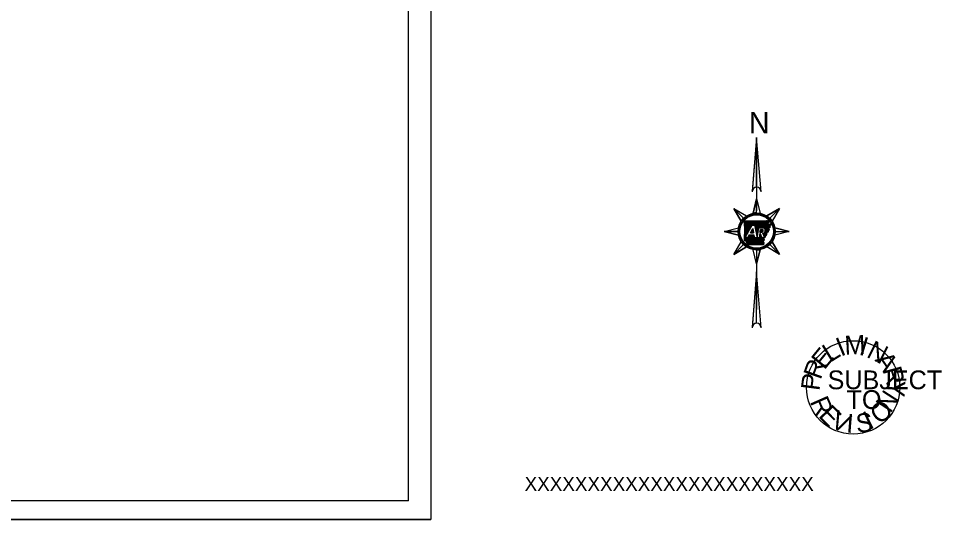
# Model space of a CAD drawing. Extents: x 1644315 to 1648839, y 578550 to 581749.
# Drawn here: x 1646874 to 1648839, y 578550 to 579616 of the extents above; entities that cross this region are included whole.
import ezdxf

# ---------------------------------------------------------------- set-up
doc = ezdxf.new("R2010")
doc.units = 0
for name, color, linetype in [('20', 7, 'Continuous'), ('R_Border PE', 7, 'Continuous'), ('R_Border Prem', 7, 'Continuous')]:
    doc.layers.add(name, color=color, linetype=linetype)

msp = doc.modelspace()

# ---------------------------------------------------------------- linework, layer by layer
at = {"layer": '20'}
msp.add_line((1644418.6, 578549.8), (1647751.9, 578549.8), dxfattribs=at)
msp.add_lwpolyline([(1644418.5, 580683.1), (1647751.9, 580683.1), (1647751.9, 578549.7), (1644418.5, 578549.7)], close=True, dxfattribs=at)
at = {"layer": 'R_Border PE'}
for q in [(1647704.4, 580644.2), (1644542.6, 578589.6)]:
    msp.add_line((1647704.4, 578589.6), q, dxfattribs=at)
at = {"layer": 'R_Border Prem'}
for p, q in [((1648445.2, 579362.9), (1648435.5, 579248.9)), ((1648445.2, 579362.9), (1648445.2, 579206.8)), ((1648445.2, 579257.1), (1648445.2, 579362.9)), ((1648435.6, 579250.5), (1648436.1, 579251)), ((1648435.7, 579251.1), (1648436.6, 579252)), ((1648445.2, 579232.2), (1648437.5, 579201.8)), ((1648445.2, 579202.5), (1648445.2, 579232.2)), ((1648396.3, 579211.9), (1648417.3, 579191)), ((1648417.3, 579191), (1648396.3, 579211.9)), ((1648396.3, 579211.9), (1648412.4, 579185)), ((1648494.1, 579211.9), (1648467.2, 579195.9)), ((1648473.2, 579191), (1648494.1, 579211.9)), ((1648473.2, 579191), (1648494.1, 579211.9)), ((1648418.3, 579185.3), (1648418.6, 579185.6)), ((1648418.4, 579184.3), (1648419.8, 579185.6)), ((1648418.5, 579183.3), (1648420.9, 579185.6)), ((1648418.7, 579182.3), (1648422, 579185.6)), ((1648418.8, 579181.3), (1648423.1, 579185.6)), ((1648418.9, 579180.3), (1648424.2, 579185.6)), ((1648419, 579179.3), (1648425.4, 579185.6)), ((1648419.2, 579178.3), (1648426.5, 579185.6)), ((1648419.3, 579177.3), (1648427.6, 579185.6)), ((1648419.4, 579176.3), (1648428.7, 579185.6)), ((1648419.5, 579175.3), (1648429.8, 579185.6)), ((1648419.7, 579174.3), (1648430.9, 579185.6)), ((1648419.8, 579173.4), (1648432.1, 579185.6)), ((1648419.9, 579161.2), (1648444.4, 579185.6)), ((1648419.9, 579172.4), (1648433.2, 579185.6)), ((1648419.9, 579160.1), (1648435, 579175.1)), ((1648419.9, 579158.9), (1648433.5, 579172.6)), ((1648420, 579162.4), (1648443.3, 579185.6)), ((1648420, 579163.5), (1648442.1, 579185.6)), ((1648420, 579171.4), (1648434.3, 579185.6)), ((1648420.1, 579164.7), (1648441, 579185.6)), ((1648420.1, 579165.8), (1648439.9, 579185.6)), ((1648420.1, 579167), (1648438.8, 579185.6)), ((1648420.2, 579168.2), (1648437.7, 579185.6)), ((1648420.2, 579169.3), (1648436.5, 579185.6)), ((1648420.2, 579170.4), (1648435.4, 579185.6)), ((1648420.3, 579149.2), (1648435.9, 579176.7)), ((1648435.9, 579176.7), (1648440.5, 579176.7)), ((1648436.5, 579176.7), (1648445.5, 579185.6)), ((1648437.7, 579176.7), (1648446.6, 579185.6)), ((1648438.8, 579176.7), (1648447.7, 579185.7)), ((1648439.9, 579176.7), (1648448.9, 579185.7)), ((1648440.6, 579176.3), (1648450, 579185.7)), ((1648440.8, 579175.4), (1648451.1, 579185.7)), ((1648441, 579174.4), (1648452.3, 579185.7)), ((1648441.2, 579173.5), (1648453.4, 579185.7)), ((1648441.4, 579172.6), (1648454.6, 579185.8)), ((1648441.6, 579171.7), (1648455.7, 579185.8)), ((1648441.8, 579170.8), (1648456.8, 579185.8)), ((1648442, 579169.8), (1648458, 579185.8)), ((1648442.2, 579168.9), (1648459.1, 579185.8)), ((1648442.4, 579168), (1648460.2, 579185.9)), ((1648442.6, 579167.1), (1648461.4, 579185.9)), ((1648442.8, 579166.2), (1648462.5, 579185.9)), ((1648443, 579165.2), (1648463.6, 579185.9)), ((1648443.2, 579164.3), (1648464.8, 579185.9)), ((1648449.9, 579171), (1648460.7, 579171)), ((1648450.9, 579171), (1648465.9, 579186)), ((1648452, 579171), (1648467.1, 579186)), ((1648453.2, 579171), (1648468.2, 579186)), ((1648454.3, 579171), (1648469.4, 579186)), ((1648455.4, 579171), (1648470.5, 579186.1)), ((1648456.5, 579171), (1648470.8, 579185.2)), ((1648457.6, 579171), (1648471.3, 579184.6)), ((1648458.7, 579171), (1648471.4, 579183.6)), ((1648459.9, 579171), (1648468.9, 579180)), ((1648460.9, 579170.9), (1648468.7, 579178.6)), ((1648461.5, 579170.3), (1648469.8, 579178.7)), ((1648462, 579169.8), (1648471, 579178.8)), ((1648462.5, 579169.1), (1648472.2, 579178.8)), ((1648462.9, 579168.4), (1648473.4, 579178.9)), ((1648463.3, 579167.7), (1648474.6, 579178.9)), ((1648463.5, 579166.8), (1648475.6, 579178.9)), ((1648463.5, 579163.4), (1648473.6, 579173.5)), ((1648463.7, 579165.8), (1648476.1, 579178.3)), ((1648463.7, 579164.7), (1648473.5, 579174.5)), ((1648472.4, 579171.1), (1648473.7, 579172.5)), ((1648475.6, 579176.7), (1648476.7, 579177.7)), ((1648514.4, 579163), (1648484, 579170.7)), ((1648376.1, 579163), (1648405.7, 579163)), ((1648405.7, 579163), (1648376.1, 579163)), ((1648376.1, 579163), (1648406.5, 579155.3)), ((1648419.6, 579152), (1648424.8, 579157.1)), ((1648419.6, 579150.8), (1648423.3, 579154.5)), ((1648419.6, 579149.7), (1648421.9, 579152)), ((1648419.7, 579154.3), (1648427.7, 579162.3)), ((1648419.7, 579153.1), (1648426.2, 579159.7)), ((1648419.8, 579157.8), (1648432.1, 579170)), ((1648419.8, 579156.6), (1648430.6, 579167.4)), ((1648419.8, 579155.4), (1648429.2, 579164.8)), ((1648419.8, 579143.2), (1648431.6, 579154.9)), ((1648420.5, 579142.7), (1648432.7, 579154.9)), ((1648421.3, 579142.4), (1648433.8, 579154.9)), ((1648422.6, 579142.6), (1648434.9, 579154.9)), ((1648423.7, 579142.7), (1648436, 579154.9)), ((1648424.6, 579141.3), (1648438.3, 579154.9)), ((1648424.6, 579142.4), (1648437.1, 579154.9)), ((1648424.7, 579140.2), (1648439.4, 579154.9)), ((1648424.7, 579139.1), (1648440, 579154.4)), ((1648424.7, 579138), (1648440.2, 579153.5)), ((1648424.7, 579136.9), (1648440.4, 579152.6)), ((1648424.7, 579135.8), (1648440.6, 579151.7)), ((1648424.7, 579134.7), (1648440.8, 579150.7)), ((1648428.9, 579154.9), (1648425.6, 579149.2)), ((1648426.9, 579151.4), (1648430.4, 579154.9)), ((1648428.4, 579154), (1648429.3, 579154.9)), ((1648439.9, 579154.9), (1648428.9, 579154.9)), ((1648431.8, 579160), (1648436.9, 579169)), ((1648431.8, 579160), (1648437.5, 579165.7)), ((1648431.8, 579160), (1648438.8, 579160)), ((1648432.9, 579160), (1648437.7, 579164.8)), ((1648433.1, 579162.4), (1648437.4, 579166.6)), ((1648434, 579160), (1648437.9, 579163.9)), ((1648434.6, 579165), (1648437.2, 579167.6)), ((1648435.2, 579160), (1648438.1, 579163)), ((1648435.8, 579134.6), (1648455.1, 579153.9)), ((1648436.1, 579167.6), (1648437, 579168.5)), ((1648436.3, 579160), (1648438.3, 579162)), ((1648437, 579134.6), (1648455.4, 579153)), ((1648437.4, 579160), (1648438.5, 579161.1)), ((1648438.1, 579134.6), (1648455.7, 579152.2)), ((1648438.5, 579160), (1648438.7, 579160.2)), ((1648439.2, 579134.6), (1648456, 579151.4)), ((1648440.3, 579134.6), (1648456.3, 579150.6)), ((1648443.4, 579163.4), (1648449.7, 579169.7)), ((1648443.6, 579162.5), (1648449.5, 579168.4)), ((1648443.7, 579161.5), (1648449.2, 579167)), ((1648443.9, 579160.6), (1648449, 579165.7)), ((1648444.1, 579159.7), (1648448.8, 579164.3)), ((1648444.3, 579158.8), (1648448.5, 579163)), ((1648444.5, 579157.9), (1648448.3, 579161.6)), ((1648444.7, 579156.9), (1648448, 579160.3)), ((1648444.9, 579156), (1648447.8, 579158.9)), ((1648445.1, 579155.1), (1648447.6, 579157.5)), ((1648445.3, 579154.2), (1648447.3, 579156.2)), ((1648445.5, 579153.3), (1648447.1, 579154.8)), ((1648445.7, 579152.3), (1648446.9, 579153.5)), ((1648445.9, 579151.4), (1648446.6, 579152.1)), ((1648446.1, 579150.5), (1648446.4, 579150.8)), ((1648450.4, 579150.3), (1648454.8, 579154.7)), ((1648450.6, 579151.6), (1648454.5, 579155.5)), ((1648450.8, 579153), (1648454.2, 579156.3)), ((1648451.1, 579154.3), (1648453.9, 579157.1)), ((1648451.3, 579155.7), (1648453.5, 579157.9)), ((1648451.5, 579157), (1648452.4, 579157.9)), ((1648453.6, 579157.9), (1648451.7, 579157.9)), ((1648452.3, 579161.2), (1648458.1, 579167.1)), ((1648452.3, 579161.2), (1648456.9, 579161.2)), ((1648452.5, 579162.5), (1648457, 579167.1)), ((1648452.7, 579163.9), (1648455.9, 579167.1)), ((1648453, 579165.2), (1648454.8, 579167.1)), ((1648453.2, 579166.6), (1648453.7, 579167.1)), ((1648453.3, 579167.1), (1648458.4, 579167.1)), ((1648453.4, 579161.2), (1648458.8, 579166.6)), ((1648456.8, 579149.2), (1648453.6, 579157.9)), ((1648454.5, 579161.2), (1648459.1, 579165.8)), ((1648455.6, 579161.2), (1648459.4, 579164.9)), ((1648456.7, 579161.2), (1648459.3, 579163.7)), ((1648458.2, 579158.2), (1648458.6, 579158.5)), ((1648458.2, 579158.4), (1648461.6, 579149.2)), ((1648458.5, 579157.3), (1648460.7, 579159.5)), ((1648458.8, 579156.5), (1648471.2, 579168.9)), ((1648459.1, 579155.7), (1648471.4, 579168)), ((1648459.4, 579154.9), (1648471.7, 579167.1)), ((1648459.7, 579154.1), (1648471.9, 579166.2)), ((1648460, 579153.3), (1648466.8, 579160)), ((1648460.4, 579152.4), (1648466.6, 579158.7)), ((1648460.7, 579151.6), (1648466.5, 579157.5)), ((1648461, 579150.8), (1648464.4, 579154.2)), ((1648461.3, 579150), (1648463.9, 579152.6)), ((1648462.5, 579161.3), (1648471, 579169.8)), ((1648468, 579161.2), (1648469.6, 579162.8)), ((1648484.8, 579163), (1648514.4, 579163)), ((1648484.8, 579163), (1648514.4, 579163)), ((1648396.3, 579114.1), (1648417.3, 579135.1)), ((1648417.3, 579135.1), (1648396.3, 579114.1)), ((1648419.4, 579143.9), (1648424.7, 579149.2)), ((1648419.4, 579145), (1648423.5, 579149.2)), ((1648419.4, 579146.2), (1648422.4, 579149.2)), ((1648419.5, 579148.5), (1648420.4, 579149.4)), ((1648419.5, 579147.3), (1648421.3, 579149.2)), ((1648425.6, 579149.2), (1648420.3, 579149.2)), ((1648425.8, 579134.7), (1648441, 579149.8)), ((1648426.9, 579134.7), (1648441.4, 579149.2)), ((1648428, 579134.7), (1648442.5, 579149.2)), ((1648429.1, 579134.6), (1648443.7, 579149.2)), ((1648430.3, 579134.6), (1648444.8, 579149.2)), ((1648431.4, 579134.6), (1648445.9, 579149.2)), ((1648432.5, 579134.6), (1648447, 579149.2)), ((1648433.6, 579134.6), (1648448.1, 579149.2)), ((1648434.7, 579134.6), (1648449.3, 579149.2)), ((1648450.2, 579149.2), (1648441.1, 579149.2)), ((1648441.4, 579134.6), (1648456.6, 579149.8)), ((1648442.5, 579134.6), (1648457.1, 579149.2)), ((1648443.7, 579134.6), (1648458.2, 579149.2)), ((1648444.8, 579134.6), (1648459.3, 579149.2)), ((1648445.9, 579134.6), (1648460.4, 579149.2)), ((1648447, 579134.6), (1648460.8, 579148.4)), ((1648448.1, 579134.6), (1648460.9, 579147.4)), ((1648449.2, 579134.6), (1648460.9, 579146.3)), ((1648450.4, 579134.6), (1648461, 579145.2)), ((1648451.5, 579134.6), (1648459.1, 579142.3)), ((1648452.6, 579134.6), (1648459.5, 579141.5)), ((1648453.7, 579134.6), (1648459.8, 579140.7)), ((1648454.8, 579134.6), (1648460.2, 579139.9)), ((1648455.9, 579134.6), (1648460.5, 579139.2)), ((1648461.6, 579149.2), (1648456.8, 579149.2)), ((1648457, 579134.6), (1648460.8, 579138.3)), ((1648458.2, 579134.6), (1648460.3, 579136.7)), ((1648459.3, 579134.6), (1648459.8, 579135.1)), ((1648473.2, 579135.1), (1648494.1, 579114.1)), ((1648473.2, 579135.1), (1648494.1, 579114.1)), ((1648494.1, 579114.1), (1648478.1, 579141)), ((1648396.3, 579114.1), (1648423.3, 579130.2)), ((1648445.2, 579093.8), (1648452.9, 579124.2)), ((1648445.2, 579123.5), (1648445.2, 579123.5)), ((1648445.2, 579123.5), (1648445.2, 578997)), ((1648445.2, 579123.5), (1648445.2, 579093.8)), ((1648445.2, 579077.3), (1648435.5, 578959.4)), ((1648445.2, 578967.7), (1648445.2, 579077.3))]:
    msp.add_line(p, q, dxfattribs=at)
for points in [[(1648455.1, 579247.3), (1648445.2, 579362.9), (1648435.4, 579247.3)], [(1648437.5, 579201.8), (1648445.2, 579232.2), (1648452.9, 579201.8)], [(1648412.4, 579185), (1648396.3, 579211.9), (1648423.3, 579195.9)], [(1648467.2, 579195.9), (1648494.1, 579211.9), (1648478.1, 579185)], [(1648406.5, 579155.3), (1648376.1, 579163), (1648406.5, 579170.7)], [(1648418.3, 579185.6), (1648433.7, 579185.6), (1648447.2, 579185.7), (1648463.2, 579185.9), (1648470.6, 579186.1)], [(1648419.4, 579143.9), (1648420.2, 579169.8), (1648418.3, 579185.6)], [(1648440.5, 579176.7), (1648446.2, 579149.9), (1648449.9, 579171)], [(1648475.4, 579179), (1648476.8, 579177.6), (1648473.4, 579174.9), (1648473.8, 579172.1), (1648470.9, 579170.2), (1648471.9, 579166), (1648469.7, 579164), (1648469.5, 579161.8), (1648466.8, 579160.8), (1648466.4, 579156.7), (1648464.5, 579154.6), (1648463.6, 579151.5), (1648460.8, 579149), (1648461, 579144.5), (1648459.1, 579142.3), (1648460.8, 579138.5), (1648459.6, 579134.6)], [(1648468.3, 579178.6), (1648475.5, 579179)], [(1648484, 579170.7), (1648514.4, 579163), (1648484, 579155.3)], [(1648436.9, 579169), (1648438.8, 579160)], [(1648441.1, 579149.2), (1648439.9, 579154.9)], [(1648451.7, 579157.9), (1648450.2, 579149.2)], [(1648452.3, 579161.2), (1648453.3, 579167.1)], [(1648423.3, 579130.2), (1648396.3, 579114.1), (1648412.4, 579141)], [(1648459.6, 579134.6), (1648424.7, 579134.7), (1648424.6, 579142.4)], [(1648478.1, 579141), (1648494.1, 579114.1), (1648467.2, 579130.2)], [(1648452.9, 579124.2), (1648445.2, 579093.8), (1648437.5, 579124.2)], [(1648455.1, 578957.8), (1648445.2, 579077.3), (1648435.4, 578957.8)]]:
    msp.add_lwpolyline(points, dxfattribs=at)
for centre, radius in [((1648445.2, 579163), 39.5), ((1648445.2, 579163), 37.5), ((1648445.2, 579163), 35.6), ((1648650.6, 578831.1), 99.4)]:
    msp.add_circle(centre, radius, dxfattribs=at)
for centre, radius, start, end in [((1648445.2, 579247.3), 9.88, 0, 180), ((1648445.2, 579247.3), 9.88, 90, 170.2296), ((1648445.2, 579163), 39.5, 135, 146.2291), ((1648445.2, 579163), 39.5, 90, 101.2291), ((1648445.2, 579163), 39.5, 45, 56.2291), ((1648456.7, 579165.2), 7, 281.8626, 54.8705), ((1648445.2, 579163), 39.5, 0, 11.2291), ((1648445.2, 579163), 39.5, 180, 191.2291), ((1648455.8, 579164.6), 3.58, 288.1268, 43.8902), ((1648445.2, 579163), 39.5, 225, 236.2291), ((1648445.2, 579163), 39.5, 315, 326.2291), ((1648445.2, 579163), 39.5, 270, 281.2291), ((1648445.2, 578957.8), 9.88, 0, 180), ((1648445.2, 578957.8), 9.88, 90, 170.5511)]:
    msp.add_arc(centre, radius, start, end, dxfattribs=at)
for points in [[(1648470.6, 579186.1), (1648470.6, 579185.7), (1648470.8, 579185.4), (1648470.8, 579185), (1648470.9, 579184.9), (1648471.2, 579184.7), (1648471.5, 579184.4), (1648471.5, 579184.1), (1648471.4, 579183.8), (1648471.4, 579183.4), (1648471.4, 579183.1), (1648471.3, 579182.8), (1648471.1, 579182.5), (1648470.9, 579182.4), (1648470.7, 579182.2), (1648470.5, 579181.9), (1648470.3, 579181.7), (1648470, 579181.5), (1648469.8, 579181.3), (1648469.6, 579181), (1648469.5, 579180.7), (1648469.3, 579180.5), (1648469.2, 579180.3), (1648468.9, 579180), (1648468.8, 579179.8), (1648468.6, 579179.5), (1648468.5, 579179.2), (1648468.4, 579179), (1648468.4, 579178.9)], [(1648424.6, 579142.4), (1648424.7, 579142.4), (1648424.5, 579142.5), (1648424.3, 579142.6), (1648424, 579142.6), (1648423.6, 579142.7), (1648423.3, 579142.7), (1648423, 579142.9), (1648422.7, 579142.7), (1648422.3, 579142.5), (1648422.1, 579142.7), (1648421.9, 579142.6), (1648421.7, 579142.6), (1648421.3, 579142.4), (1648421, 579142.5), (1648420.8, 579142.4), (1648420.5, 579142.4), (1648420.4, 579142.8), (1648420.2, 579142.8), (1648419.9, 579143), (1648419.8, 579143.3), (1648419.6, 579143.5), (1648419.4, 579143.9)]]:
    msp.add_spline(points, degree=3, dxfattribs=at)

# ---------------------------------------------------------------- texts
at = {"layer": 'R_Border PE'}
msp.add_text('XXXXXXXXXXXXXXXXXXXXXXX', height=30, dxfattribs=at).set_placement((1647951.3, 578610.6))
at = {"layer": 'R_Border Prem'}
for s, height, p in [('N', 45.6, (1648428.6, 579371.8)), ('DWB 7-27-17', 0.768, (1648442.8, 579126.8)), ('SUBJECT', 40, (1648596.2, 578827.1)), ('TO', 40, (1648636.6, 578785.1))]:
    msp.add_text(s, height=height, dxfattribs=at).set_placement(p)
for s, rotation, p in [('I', 22.0105, (1648624.3, 578896.3)), ('M', 2.6943, (1648633, 578900.6)), ('I', 343.3781, (1648661.2, 578901.3)), ('E', 50.9849, (1648589.3, 578867)), ('L', 31.6686, (1648601.1, 578883.1)), ('N', 333.7199, (1648677, 578896.5)), ('A', 304.7456, (1648695.7, 578889.4)), ('R', 70.3011, (1648581.3, 578845.9)), ('R', 285.4294, (1648713, 578869.2)), ('P', 82.6089, (1648578.7, 578822.7)), ('Y', 266.1131, (1648722.2, 578847.7)), ('N', 57.1378, (1648729.7, 578774.7)), ('R', 293.7639, (1648557.9, 578800.9)), ('O', 36.5754, (1648705.4, 578750.9)), ('E', 314.3262, (1648575.1, 578769.5)), ('V', 334.8885, (1648599.9, 578747.7)), ('I', 26.2943, (1648685.1, 578739.9)), ('I', 355.4508, (1648635.1, 578735)), ('S', 5.732, (1648658.3, 578734.3))]:
    msp.add_text(s, height=40, rotation=rotation, dxfattribs=at).set_placement(p)

doc.saveas('drawing.dxf')
